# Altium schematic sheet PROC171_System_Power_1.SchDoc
size 431 x 279 mm; Date: Not shown in title block; ApprovedBy: Not shown in title block; CheckedBy: Not shown in title block; Author: Not shown in title block; CompanyName: Not shown in title block; Engineer: Not shown in title block; Organization: Not shown in title block; Address1: Not shown in title block; Address2: Not shown in title block; Address3: Not shown in title block; Address4: Not shown in title block; DocumentNumber: 2; Revision: Use project parameter SCH_Rev; SheetNumber: 2; SheetTotal: 26; PageSetup: Record=PageOptions¦CenterHorizontal=True¦CenterVertical=True¦PrintScale=1.00¦XCorrection=1.00¦YCorrection=1.00¦PrintKind=0¦BorderSize=5000000¦LeftOffset=0¦BottomOffset=0¦Orientation=2¦PaperLength=1000¦PaperWidth=1000¦Scale=100¦PaperSource=15¦PrintQuality=600¦MediaType=1¦DitherType=10¦PaperKind=Letter¦PrintScaleMode=1
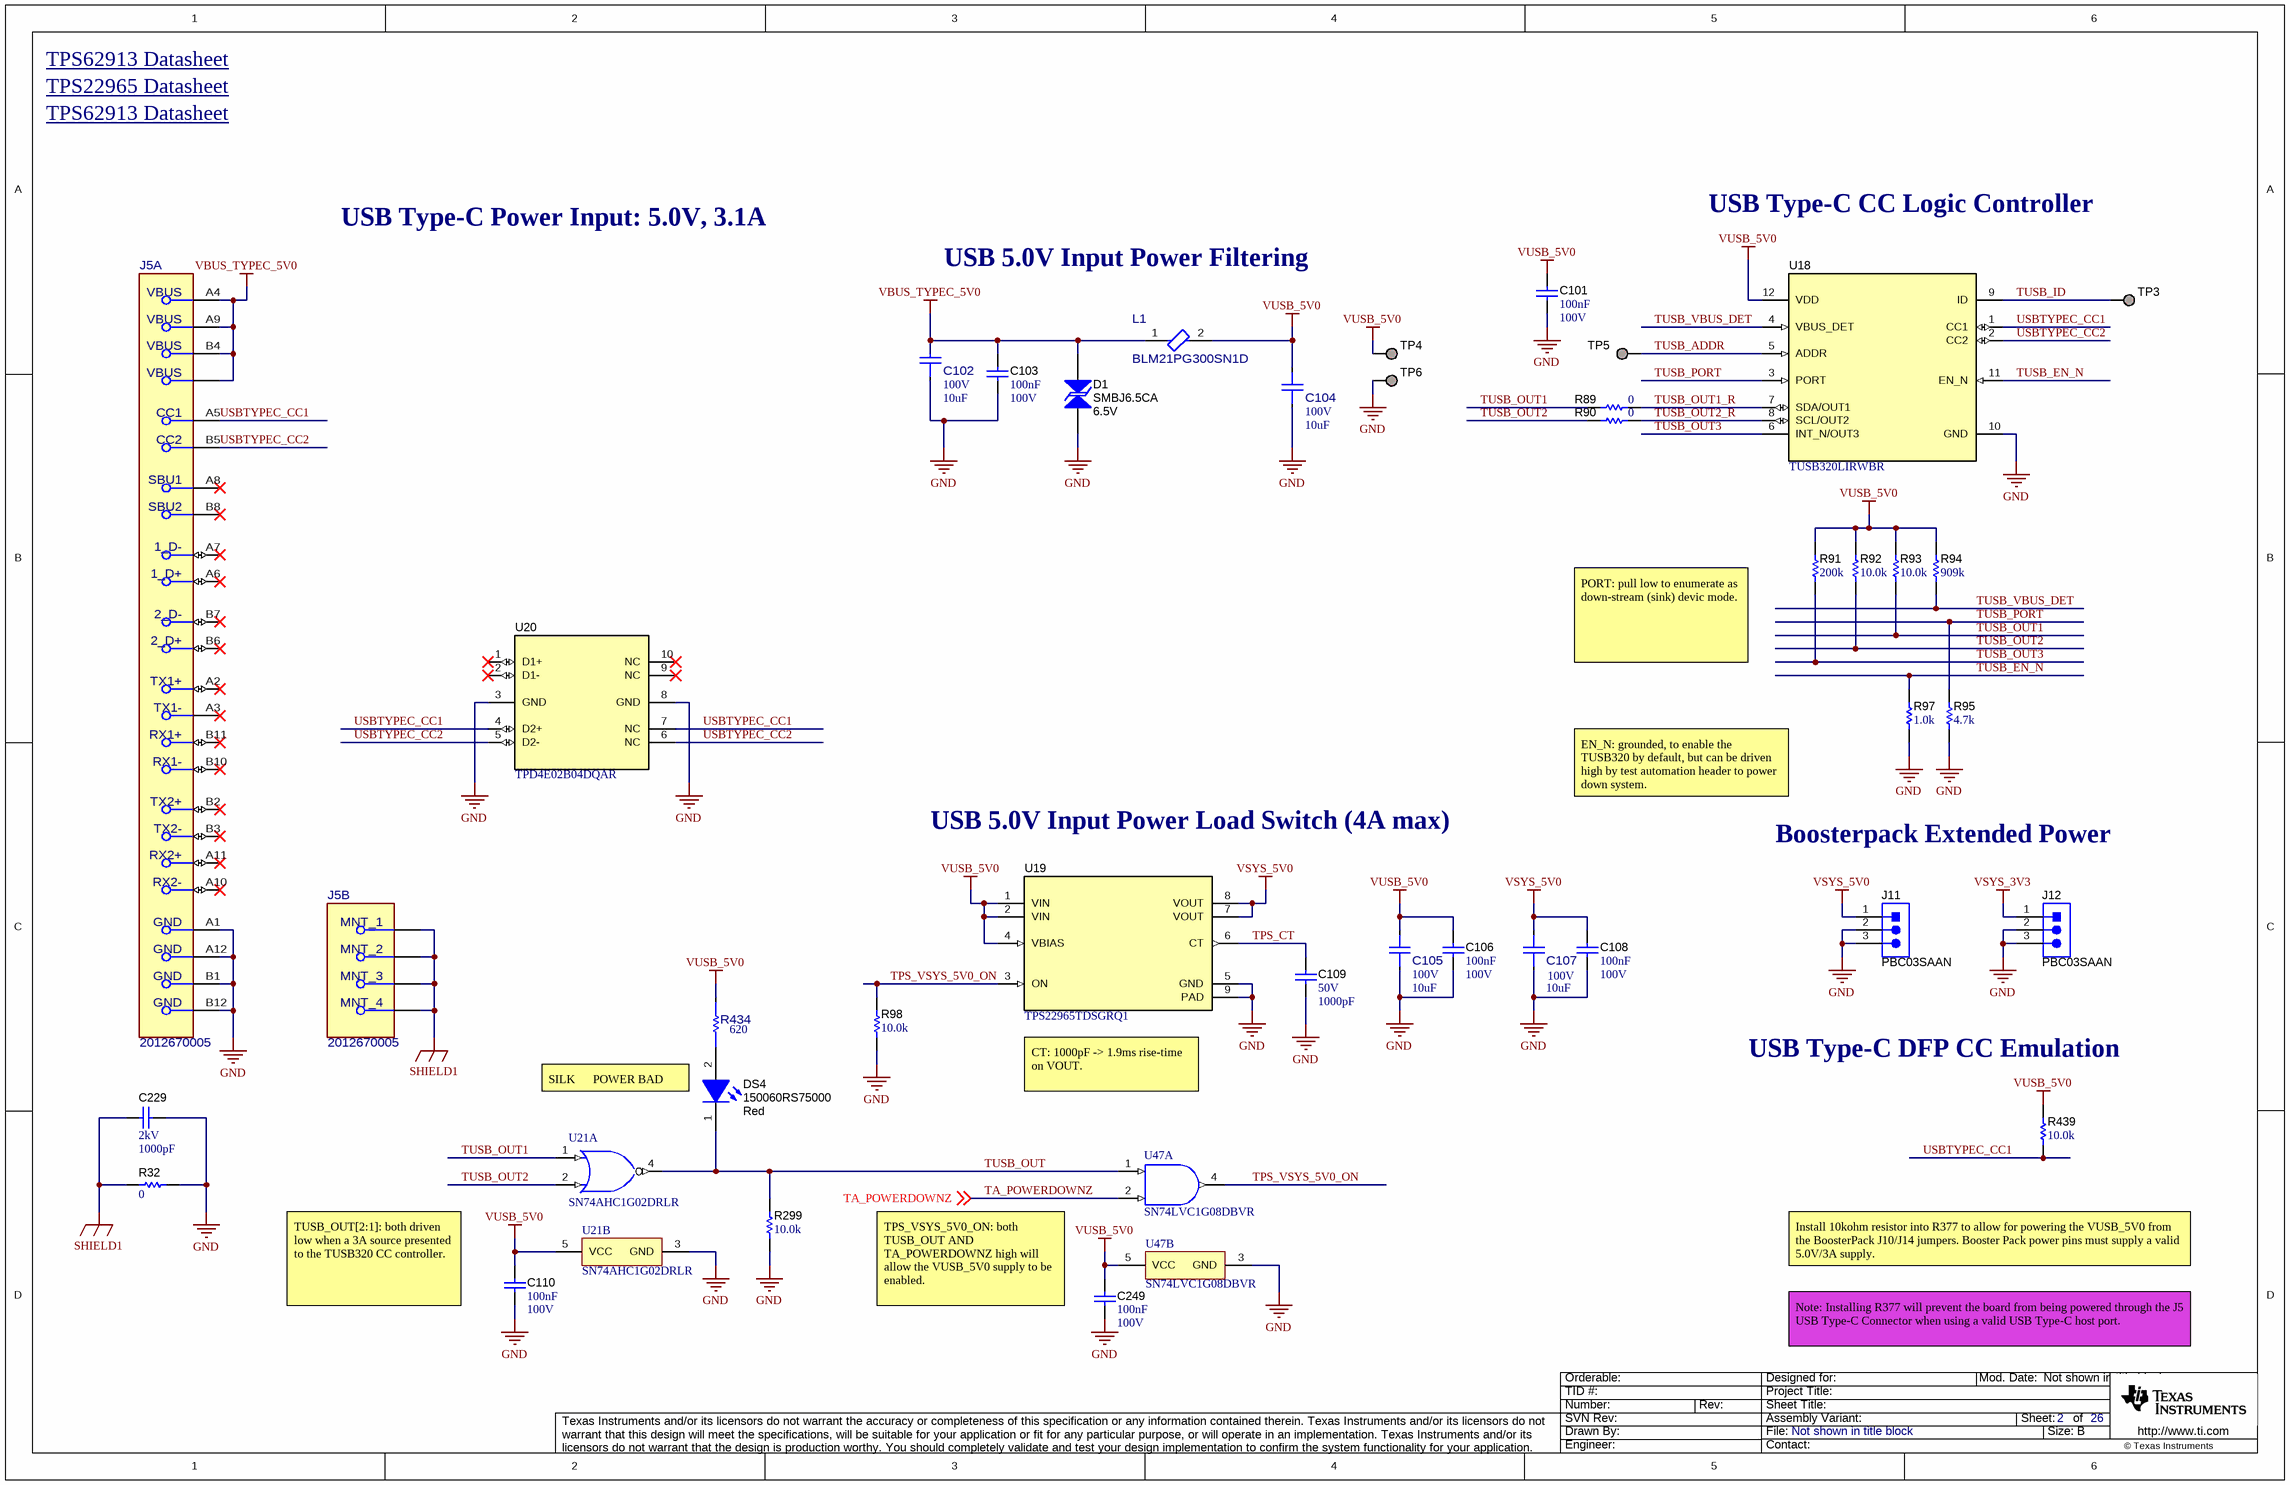
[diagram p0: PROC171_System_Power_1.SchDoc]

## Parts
C101  Cap_F: 100nF  VDC_V: 100V  [0603]  (hidden comment: GRM188R72A104KA35D)
C102  VDC_V: 100V  ValueDisplayed: 10uF  [FP-GRM32EC72A106KE05L_1210-MFG]  (hidden comment: GRM32EC72A106KE05L)
C103  Cap_F: 100nF  VDC_V: 100V  [0603]  (hidden comment: GRM188R72A104KA35J)
C104  VDC_V: 100V  ValueDisplayed: 10uF  [FP-GRM32EC72A106KE05L_1210-MFG]  (hidden comment: GRM32EC72A106KE05L)
C105  VDC_V: 100V  ValueDisplayed: 10uF  [FP-GRM32EC72A106KE05L_1210-MFG]  (hidden comment: GRM32EC72A106KE05L)
C106  Cap_F: 100nF  VDC_V: 100V  [0603]  (hidden comment: GRM188R72A104KA35D)
C107  VDC_V: 100V  ValueDisplayed: 10uF  [FP-GRM32EC72A106KE05L_1210-MFG]  (hidden comment: GRM32EC72A106KE05L)
C108  Cap_F: 100nF  VDC_V: 100V  [0603]  (hidden comment: GRM188R72A104KA35D)
C109  VDC_V: 50V  ValueDisplayed: 1000pF  [0402]  (hidden comment: GRM1555C1H102JA01D)
C110  Cap_F: 100nF  VDC_V: 100V  [0603]  (hidden comment: GRM188R72A104KA35D)
C229  VDC_V: 2kV  ValueDisplayed: 1000pF  [1808]  (hidden comment: GR442QR73D102KW01L)
C249  Cap_F: 100nF  VDC_V: 100V  [0603]  (hidden comment: GRM188R72A104KA35D)
D1  SMBJ6.5CA  value 6.5V  [SMB-Bi]
DS4  150060RS75000  value Red  [WL-SMCW_RED]
J5  2012670005  [FP-2012670005_CONN_USB_9MM39_8MM21-MFG]  (parts A,B of 2)
J11  PBC03SAAN  [PBC03SAAN]
J12  PBC03SAAN  [PBC03SAAN]
L1  BLM21PG300SN1D  [FP-BLM21PG300SN1D_0805-MFG]
R32  ValueDisplayed: 0  [0805_HV]  (hidden comment: ERJ-6GEY0R00V)
R89  ValueDisplayed: 0  [0402L]  (hidden comment: ERJ-2GE0R00X)
R90  ValueDisplayed: 0  [0402L]  (hidden comment: ERJ-2GE0R00X)
R91  ValueDisplayed: 200k  [0402]  (hidden comment: CRCW0402200KJNED)
R92  ValueDisplayed: 10.0k  [0402]  (hidden comment: ERJ-2RKF1002X)
R93  ValueDisplayed: 10.0k  [0402]  (hidden comment: ERJ-2RKF1002X)
R94  ValueDisplayed: 909k  [0402]  (hidden comment: CRCW0402909KFKED)
R95  ValueDisplayed: 4.7k  [0402]  (hidden comment: CRCW04024K70JNED)
R97  ValueDisplayed: 1.0k  [0402]  (hidden comment: ERJ-2GEJ102X)
R98  ValueDisplayed: 10.0k  [0402]  (hidden comment: ERJ-2RKF1002X)
R299  ValueDisplayed: 10.0k  [0402]  (hidden comment: ERJ-2RKF1002X)
R434  value 620  [FP-ERA-2APB621X_0402-MFG]  (hidden comment: ERA-2APB621X)
R439  ValueDisplayed: 10.0k  [0402]  (hidden comment: ERJ-2RKF1002X)
TP3  TESTPOINT  [TP_25MIL-SMT]  (value not drawn)  (no BOM)
TP4  TESTPOINT  [TP_25MIL-SMT]  (value not drawn)  (no BOM)
TP5  TESTPOINT  [TP_25MIL-SMT]  (value not drawn)  (no BOM)
TP6  TESTPOINT  [TP_25MIL-SMT]  (value not drawn)  (no BOM)
U18  TUSB320LIRWBR  [RWB0012A]
U19  TPS22965TDSGRQ1  [DSG0008B]
U20  TPD4E02B04DQAR  [DQA0010A]
U21  SN74AHC1G02DRLR  [DRL0005A]  (parts A,B of 2)
U47  SN74LVC1G08DBVR  [DBV0005A_N]  (parts A,B of 2)

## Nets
GND: C101.2 C102.1 C103.2 C104.1 C105.1 C106.2 C107.1 C108.2 C109.2 C110.2 C229.1 C249.2 D1.1 J5.A1(GND) J5.A12(GND) J5.B1(GND) J5.B12(GND) J11.2 J11.3 J12.2 J12.3 R32.2 R95.1 R97.1 R98.2 R299.2 TP6.1 U18.10(GND) U19.5(GND) U19.9(PAD) U20.3(GND) U20.8(GND) U21.3(GND) U47.3(GND)
SHIELD1: C229.2 J5.1(MNT_1) J5.2(MNT_2) J5.3(MNT_3) J5.4(MNT_4) R32.1
VBUS_TYPEC_5V0: C102.2 C103.1 D1.2 J5.A4(VBUS) J5.A9(VBUS) J5.B4(VBUS) J5.B9(VBUS) L1.1
VSYS_3V3: J12.1
VSYS_5V0: C107.2 C108.1 J11.1 U19.7(VOUT) U19.8(VOUT)
VUSB_5V0: C101.1 C104.2 C105.2 C106.1 C110.1 C249.1 L1.2 R91.2 R92.1 R93.1 R94.2 R434.2 R439.1 TP4.1 U18.12(VDD) U19.1(VIN) U19.2(VIN) U19.4(VBIAS) U21.5(VCC) U47.5(VCC)
TA_POWERDOWNZ: U47.2(B) ; off-sheet TA_POWERDOWNZ
TPS_CT: C109.1 U19.6(CT)
TPS_VSYS_5V0_ON: R98.1 U19.3(ON) U47.4(Y)
TUSB_ADDR: TP5.1 U18.5(ADDR)
TUSB_EN_N: R97.2 U18.11(EN_N)
TUSB_ID: TP3.1 U18.9(ID)
TUSB_OUT: DS4.1(K) R299.1 U21.4(Y) U47.1(A)
TUSB_OUT1: R89.2 R93.2 U21.1(A)
TUSB_OUT1_R: R89.1 U18.7(SDA/OUT1)
TUSB_OUT2: R90.2 R92.2 U21.2(B)
TUSB_OUT2_R: R90.1 U18.8(SCL/OUT2)
TUSB_OUT3: R91.1 U18.6(INT_N/OUT3)
TUSB_PORT: R95.2 U18.3(PORT)
TUSB_VBUS_DET: R94.1 U18.4(VBUS_DET)
USBTYPEC_CC1: J5.A5(CC1) R439.2 U18.1(CC1) U20.4(D2+) U20.7(NC)
USBTYPEC_CC2: J5.B5(CC2) U18.2(CC2) U20.5(D2-) U20.6(NC)
NetDS4_2: DS4.2(A) R434.1

Not connected (* = marked no-connect by the designer): J5 A2(TX1+)* A3(TX1-)* A6(1_D+)* A7(1_D-)* A8(SBU1)* A10(RX2-)* A11(RX2+)* B2(TX2+)* B3(TX2-)* B6(2_D+)* B7(2_D-)* B8(SBU2)* B10(RX1-)* B11(RX1+)*; U20 1(D1+)* 2(D1-)* 9(NC)* 10(NC)*

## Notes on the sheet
- TPS62913 Datasheet <https://www.ti.com/product/TPS62913>
- TPS22965 Datasheet <http://www.ti.com/lit/ds/symlink/tps22965-q1.pdf>
- TPS62913 Datasheet <datasheets/IC-TPS62913RPUR.pdf>
- USB Type-C Power Input: 5.0V, 3.1A
- USB Type-C CC Logic Controller
- USB 5.0V Input Power Filtering
- PORT: pull low to enumerate as down-stream (sink) devic mode.
- USB 5.0V Input Power Load Switch (4A max)
- EN_N: grounded, to enable the TUSB320 by default, but can be driven high by test automation header to power down system.
  TA_POWERDOWNZ: pulled high by default. Can be driven low by TA Header to disable USB 5.0V supply.
- Boosterpack Extended Power
- SILK      POWER BAD
- (near U19) CT: 1000pF -> 1.9ms rise-time on VOUT.
- USB Type-C DFP CC Emulation
- TUSB_OUT[2:1]: both driven low when a 3A source presented to the TUSB320 CC controller.
- (near C249) TPS_VSYS_5V0_ON: both TUSB_OUT AND TA_POWERDOWNZ high will allow the VUSB_5V0 supply to be enabled.
- Install 10kohm resistor into R377 to allow for powering the VUSB_5V0 from the BoosterPack J10/J14 jumpers. Booster Pack power pins must supply a valid 5.0V/3A supply.
- Note: Installing R377 will prevent the board from being powered through the J5 USB Type-C Connector when using a valid USB Type-C host port.

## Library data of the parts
C101 C106 C108 C110 C249 = CMP-0007469-4: CAP, CERM, 0.1 uF, 100 V, +/- 10%, X7R, 0603; Manufacturer: MuRata; TaMin_C: -55°C; Polarized: N; SizeAreaWB_mm2: 4.68; Value1: Unknown; U/M: EA; Value: 0.1uF; TaMax_C: 125°C; SizeZ_mm: 1; SizeX_mm: 1.6; SizeY_mm: 0.8; SizeArea_mm2: 1.28; AEC Category: Q200
C102 C104 C105 C107 = CMP-0087970-1: 10µF ±10% 100V Ceramic Capacitor X7S 1210 (3225 Metric); Manufacturer: Murata; TempCo: 22%; SizeZ_mm: 2.7mm; AEC Qualified: No; Symbol Name: SYM-GRM32EC72A106KE05L
C103 = CMP-0007470-5: CAP, CERM, 0.1 uF, 100 V, +/- 10%, X7R, 0603; Manufacturer: MuRata; TaMin_C: -55°C; Polarized: N; SizeAreaWB_mm2: 4.68; Value1: Unknown; U/M: EA; Value: 0.1uF; TaMax_C: 125°C; SizeZ_mm: 1; SizeX_mm: 1.6; SizeY_mm: 0.8; SizeArea_mm2: 1.28; AEC Category: Q200
C109 = CMP-0006412-2: CAP, CERM, 1000 pF, 50 V, +/- 5%, C0G/NP0, 0402; Manufacturer: MuRata; TaMin_C: -55°C; Polarized: N; SizeAreaWB_mm2: 3; Value1: Unknown; U/M: EA; Value: 1000pF; TaMax_C: 125°C; SizeZ_mm: 0.6; SizeX_mm: 1; SizeY_mm: 0.5; Cap_F: 1nF; AEC Category: Q200
C229 = CMP-0009436-2: CAP, CERM, 1000 pF, 2000 V, +/- 10%, X7R, 1808; Manufacturer: MuRata; TaMin_C: -55°C; Polarized: N; SizeAreaWB_mm2: 16.5; Value1: Unknown; U/M: EA; Value: 1000pF; TaMax_C: 125°C; SizeZ_mm: 2.03; SizeX_mm: 4.5; SizeY_mm: 2; Value2: 2000V; SizeArea_mm2: 9; Cap_F: 1nF; AEC Category: Q200
D1 = CMP-0005599-2: Diode, TVS, Bi, 6.5 V, SMB; Manufacturer: Littelfuse; SizeZ_mm: 2.6; SizeY_mm: 3.81; Ppk: 600W; AEC Category: Q101; RJA_CperW: 100; SizeArea_mm2: 21.336; SizeX_mm: 5.6; SizeAreaWB_mm2: 44.156
DS4 = CMP-0002947-3: LED, Red, SMD; Manufacturer: Wurth Elektronik; Value1: 0.072W; Vf_V: 2V; Angle: 140; Tjmax_C: 85°C; Type: AlInGaP; Vr_V: 5V; Io_A: 30mA; Power_TotalModule: 72mW
J5 = CMP-0093552-1: USB-C (USB TYPE-C) USB 3.2 Gen 2 (USB 3.1 Gen 2, Superspeed + (USB 3.1)) Receptacle Connector 24 Position Surface Mount, Right Angle; Through Hole; Manufacturer: Molex; Voltage_V: 30V; SizeZ_mm: 3.86mm; DUT-Pitch_mm: 0.5mm; Shrouded: true; ContactFinish: Gold,Nickel; Usb Standard: USB 3.1; AEC Qualified: No; Is Female: yes
J11 J12 = CMP-0002334-1: Header, 100mil, 3x1, Gold, TH; Manufacturer: Sullins Connector Solutions; CNHeader: TRUE; Green_Lifecycle: Not Set; Green_REACh: Incomplete; CT: FALSE
L1 = CMP-0098084-1: Chip Ferrite Bead, 0805, 30Ω @ 100MHz, 0.014Ω, , 4A; Manufacturer: Murata; DCR_ohm: 14m; SizeZ_mm: 1.05mm; Ciiva Ids: 886678; Import Ts: 1521843479; AEC Qualified: No
R32 = CMP-0020616-3: RES, 0, 5%, 0.125 W, AEC-Q200 Grade 0, 0805; Manufacturer: Panasonic; Power_W: 125mW; TempCo: 600 ppm/C; Value_Code: 0000; Value: 0; EIA_Code: E24; SizeX_mm: 2; SizeY_mm: 1.25; SizeZ_mm: 1.45; Value2: 0.125W; SizeArea_mm2: 2.5; AEC Qualified: Y; VDC_V: 150V; AEC Category: Q200; SizeAreaWB_mm2: 6.75
R89 R90 = CMP-0026992-3: RES, 0, 5%, 0.1 W, AEC-Q200 Grade 0, 0402; Manufacturer: Panasonic; Power_W: 100mW; TempCo: 600 ppm/C; Value_Code: 0000; Value: 0; EIA_Code: E24; SizeX_mm: 1; SizeY_mm: 0.5; SizeZ_mm: 0.6; Value2: 0.1W; AEC Qualified: Y; VDC_V: 50V; AEC Category: Q200; SizeAreaWB_mm2: 3
R91 = CMP-0026873-2: RES, 200 k, 5%, 0.063 W, AEC-Q200 Grade 0, 0402; Manufacturer: Vishay-Dale; Power_W: 63mW; TempCo: 200 ppm/C; Value: 200k; EIA_Code: E24; SizeX_mm: 1; SizeY_mm: 0.5; SizeZ_mm: 0.6; Value2: 0.063W; AEC Qualified: Y; VDC_V: 50V; AEC Category: Q200; AEC Grade: 0
R92 R93 R98 R299 R439 = CMP-0026658-1: RES, 10.0 k, 1%, 0.1 W, 0402; Manufacturer: Panasonic; Power_W: 100mW; TempCo: 100 ppm/C; Value_Code: 10k0; U/M: EA; Value: 10.0k; EIA_Code: E96; Res_ohm: 10k; SizeX_mm: 1; SizeY_mm: 0.5; SizeZ_mm: 0.6; Value2: 0.1W; VDC_V: 50V; AEC Category: Q200
R94 = CMP-0026603-2: RES, 909 k, 1%, 0.063 W, AEC-Q200 Grade 0, 0402; Manufacturer: Vishay-Dale; Power_W: 63mW; TempCo: 100 ppm/C; Value: 909k; EIA_Code: E96; SizeX_mm: 1; SizeY_mm: 0.5; SizeZ_mm: 0.6; Value2: 0.063W; AEC Qualified: Y; VDC_V: 50V; AEC Category: Q200; AEC Grade: 0
R95 = CMP-0026938-5: RES, 4.7 k, 5%, 0.063 W, AEC-Q200 Grade 0, 0402; Manufacturer: Vishay-Dale; Power_W: 63mW; TempCo: 200 ppm/C; Value_Code: 4k70; Value: 4.7k; EIA_Code: E24; SizeX_mm: 1; SizeY_mm: 0.5; SizeZ_mm: 0.6; Value2: 0.063W; AEC Qualified: Y; VDC_V: 50V; AEC Category: Q200; AEC Grade: 0
R97 = CMP-0078193-1: RES, 1.0 k, 5%, 0.1 W, AEC-Q200 Grade 0, 0402; Manufacturer: Panasonic; Value_Code: 1k00; SizeArea_mm2: 0.5; AEC Qualified: Y; AEC Category: Q200; Res_ohm: 1k; Value: 1.0k; SizeZ_mm: 0.6; Green_REACh: Passed; EIA_Code: E24; TempCo: 200 ppm/C; AEC Grade: 0; Power_W: 100mW; VDC_V: 50V; Value2: 0.1W; Green_Lifecycle: Active; U/M: EA; SizeX_mm: 1
R434 = CMP-0093717-1: 620 Ohms ±0.1% 0.063W, 1/16W Chip Resistor 0402 (1005 Metric) Automotive AEC-Q200 Thin Film; Manufacturer: Panasonic; VDC_V: 50V; AEC Grade: Grade 0; TempCo: 15ppm/°C; AEC Qualified: Yes; SizeZ_mm: 0.4mm; Power_W: 63mW
TP3-TP6 = CMP-0078143-3: TEST POINT.  No entry in BOM.
U18 = CMP-0073635-2: USB Type-C Configuration Channel Logic and Port Control, RWB0012A (X2QFN-12); Alternate Manufacturer: Texas Instruments; SizeAreaWB_mm2: 6.76; SizeZ_mm: 0.4; SizeX_mm: 1.6; SizeArea_mm2: 2.56; CompType: IC; AEC Category: Q200; AEC Qualified: N; Rating: Catalog
U19 = CMP-0073678-3: 5.5V, 4A, 16mΩ Automotive Load Switch With Adjustable Rise Time and Optional Quick Output Discharge, DSG0008B (WSON-8); Alternate PartNumber: TPS22965TDSGTQ1; Alternate Manufacturer: Texas Instruments; Green_Lifecycle: Active; SizeAreaWB_mm2: 9.0; Green_REACh: Passed; U/M: EA; SizeZ_mm: 0.8; SizeX_mm: 2.0; SizeArea_mm2: 4.0; CompType: IC; AEC Category: Q200; AEC Qualified: Y
U20 = CMP-0073612-3: 4-Channel ESD Protection Diode for USB Type-C and HDMI 2.0, DQA0010A (USON-10); Alternate Manufacturer: Texas Instruments; Green_Lifecycle: Active; SizeAreaWB_mm2: 7.0; Green_REACh: Passed; SizeZ_mm: 0.55; SizeX_mm: 1.0; SizeY_mm: 2.5; CompType: IC; AEC Category: Q200; AEC Qualified: Y
U21 = CMP-0051530-2: Single 2-Input Positive-NOR Gate, DRL0005A, LARGE T&R; Manufacturer: Texas Instruments; Schmitt Trigger: No; Technology Family: AHC; Logic: True; Gate Type: NOR; Output Type: CMOS; Sub-Family: NAND Gate; Rating: Catalog; F @ Nom Voltage(Max)(Mhz): 75; ICC @ Nom Voltage(Max)(mA): 0.01; tpd @ Nom Voltage(Max)(ns): 11.4,7.5; Voltage(Nom)(V): 3.3,5; Output Drive (IOL/IOH)(Max)(mA): 50/-50; VCC(Max)(V): 5.5; VCC(Min)(V): 2; Bits(#): 1; AEC Category: Q200; AEC Qualified: N; CompType: IC; SizeArea_mm2: 2.56; SizeX_mm: 1.6; SizeZ_mm: 0.6
U47 = CMP-0051588-2: Single 2-Input Positive-AND Gate, DBV0005A, LARGE T&R; Manufacturer: Texas Instruments; Logic: True; ICC @ Nom Voltage(Max)(mA): 0.01; VCC(Min)(V): 1.65; Bits(#): 1; Rating: Catalog; Schmitt Trigger: No; Voltage(Nom)(V): 1.8,2.5,3.3,5; Output Drive (IOL/IOH)(Max)(mA): 32/-32; Gate Type: AND; tpd @ Nom Voltage(Max)(ns): 4.5,6,4,5; VCC(Max)(V): 5.5; Output Type: CMOS; F @ Nom Voltage(Max)(Mhz): 150; Input Type: CMOS/TTL; Technology Family: LVC; AEC Category: Q200; AEC Qualified: N; CompType: IC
